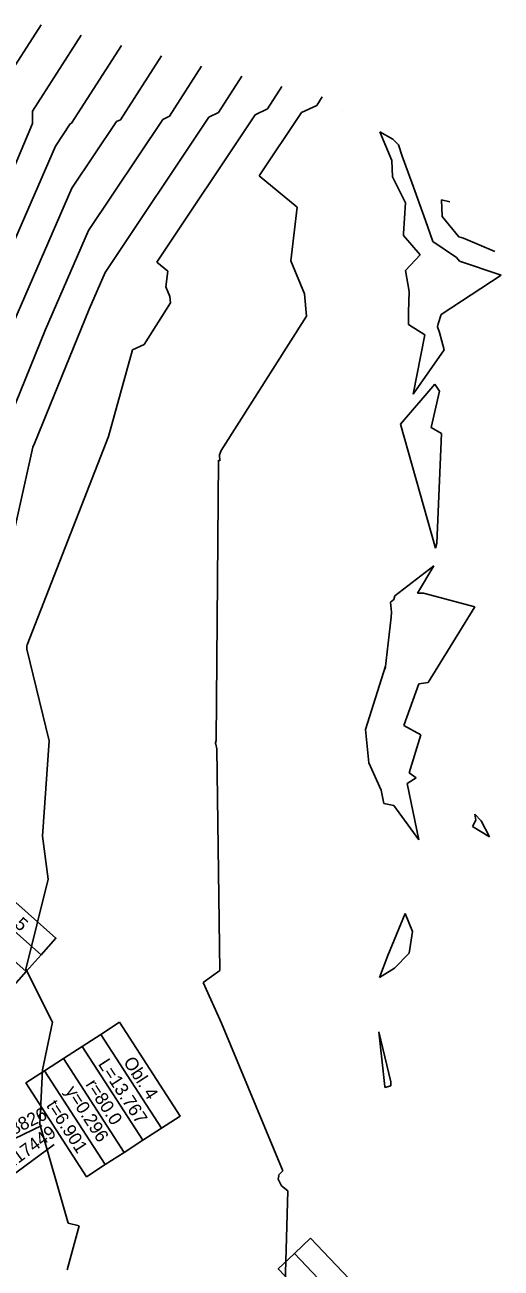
# Model space of a CAD drawing. Extents: x -549394 to -546608, y -1037055 to -1033629.
# Drawn here: x -547749.6 to -547621.7, y -1034785.5 to -1034451.5 of the extents above; entities that cross this region are included whole.
import ezdxf

# ---------------------------------------------------------------- set-up
doc = ezdxf.new("R2010")
doc.units = 0
for name, color, linetype in [('hlavni_vrst', 7, 'Continuous'), ('norm_vrst', 7, 'Continuous'), ('x_popis_oblouky_C21', 7, 'Continuous')]:
    doc.layers.add(name, color=color, linetype=linetype)

msp = doc.modelspace()

# ---------------------------------------------------------------- linework, layer by layer
at = {"layer": 'hlavni_vrst'}
for p, q in [((-547712.93, -1034459.83), (-547723.93, -1034477.01)), ((-547664.37, -1034474.53), (-547664.37, -1034474.53)), ((-547664.37, -1034474.53), (-547664.37, -1034474.53)), ((-547664.37, -1034474.53), (-547664.37, -1034474.53)), ((-547664.37, -1034474.53), (-547664.37, -1034474.53)), ((-547664.37, -1034474.53), (-547664.37, -1034474.53)), ((-547725.04, -1034477.54), (-547737, -1034495.44)), ((-547723.93, -1034477.01), (-547725.04, -1034477.54)), ((-547654.29, -1034480.26), (-547651.03, -1034487.95)), ((-547650.78, -1034482.28), (-547654.29, -1034480.26)), ((-547649.26, -1034483.72), (-547650.78, -1034482.28)), ((-547648.25, -1034486.79), (-547649.26, -1034483.72)), ((-547651.03, -1034487.95), (-547650.86, -1034492.35)), ((-547645.71, -1034493.87), (-547648.25, -1034486.79)), ((-547650.86, -1034492.35), (-547647.36, -1034499.32)), ((-547737, -1034495.44), (-547755.79, -1034538.71)), ((-547642.03, -1034504.09), (-547645.71, -1034493.87)), ((-547647.36, -1034499.32), (-547647.95, -1034507.59)), ((-547637.73, -1034498.55), (-547637.56, -1034503)), ((-547637.73, -1034498.55), (-547635.46, -1034499.05)), ((-547637.56, -1034503), (-547633.02, -1034508.52)), ((-547640.09, -1034509.72), (-547642.03, -1034504.09)), ((-547647.95, -1034507.59), (-547647.89, -1034508.12)), ((-547647.89, -1034508.12), (-547643.46, -1034513.35)), ((-547633.7, -1034514.04), (-547640.09, -1034509.72)), ((-547631.77, -1034508.8), (-547633.02, -1034508.52)), ((-547631.77, -1034508.8), (-547623.37, -1034512.46)), ((-547643.46, -1034513.35), (-547647.4, -1034517.48)), ((-547632.88, -1034515.03), (-547633.7, -1034514.04)), ((-547621.7, -1034518.79), (-547632.88, -1034515.03)), ((-547647.4, -1034517.48), (-547646.4, -1034523.19)), ((-547637.79, -1034529.35), (-547621.7, -1034518.79)), ((-547646.4, -1034523.19), (-547646.62, -1034528.71)), ((-547646.62, -1034528.71), (-547646.62, -1034532.01)), ((-547638.66, -1034531.86), (-547637.79, -1034529.35)), ((-547646.62, -1034532.01), (-547642.2, -1034534.79)), ((-547638.82, -1034532.68), (-547638.66, -1034531.86)), ((-547638.22, -1034534.17), (-547638.82, -1034532.68)), ((-547642.2, -1034534.79), (-547645.32, -1034550.77)), ((-547636.97, -1034538.86), (-547638.22, -1034534.17)), ((-547645.32, -1034550.77), (-547636.97, -1034538.86)), ((-547639.51, -1034548.01), (-547648.69, -1034558.82)), ((-547640.53, -1034559.73), (-547638.29, -1034549.93)), ((-547638.29, -1034549.93), (-547639.51, -1034548.01)), ((-547648.69, -1034558.82), (-547639.29, -1034592.12)), ((-547637.75, -1034561.3), (-547640.53, -1034559.73)), ((-547638.93, -1034590.72), (-547637.75, -1034561.3)), ((-547639.29, -1034592.12), (-547638.93, -1034590.72)), ((-547639.76, -1034596.89), (-547650.23, -1034604.9)), ((-547644.2, -1034604.16), (-547639.76, -1034596.89)), ((-547650.56, -1034605.87), (-547651.46, -1034606.64)), ((-547651.46, -1034606.64), (-547651.16, -1034609.31)), ((-547650.23, -1034604.9), (-547650.56, -1034605.87)), ((-547642.55, -1034604.2), (-547644.2, -1034604.16)), ((-547628.81, -1034607.85), (-547642.55, -1034604.2)), ((-547651.16, -1034609.31), (-547651.28, -1034610.61)), ((-547641.31, -1034628.2), (-547628.81, -1034607.85)), ((-547651.28, -1034610.61), (-547652.83, -1034624.61)), ((-547652.78, -1034623.84), (-547658.12, -1034640.81)), ((-547652.83, -1034624.61), (-547652.78, -1034623.84)), ((-547647.81, -1034639.72), (-547643.84, -1034628.54)), ((-547643.84, -1034628.54), (-547641.31, -1034628.2)), ((-547643.25, -1034642.23), (-547647.81, -1034639.72)), ((-547658.12, -1034640.81), (-547657.27, -1034649.76)), ((-547646.42, -1034652.42), (-547643.25, -1034642.23)), ((-547657.27, -1034649.76), (-547653.97, -1034657.12)), ((-547644.49, -1034653.75), (-547646.42, -1034652.42)), ((-547646.96, -1034655.34), (-547644.49, -1034653.75)), ((-547643.8, -1034670.42), (-547646.96, -1034655.34)), ((-547653.97, -1034657.12), (-547653.18, -1034660.66)), ((-547653.18, -1034660.66), (-547650.49, -1034661.19)), ((-547650.49, -1034661.19), (-547643.8, -1034670.42)), ((-547628.53, -1034665.15), (-547629.42, -1034666.89)), ((-547627.09, -1034665.35), (-547628.74, -1034663.55)), ((-547628.74, -1034663.55), (-547628.53, -1034665.15)), ((-547624.83, -1034669.63), (-547627.09, -1034665.35)), ((-547629.42, -1034666.89), (-547624.83, -1034669.63)), ((-547647.44, -1034690.27), (-547652.17, -1034701.54)), ((-547645.47, -1034695.06), (-547647.44, -1034690.27)), ((-547646.44, -1034700.91), (-547645.47, -1034695.06)), ((-547652.17, -1034701.54), (-547654.37, -1034707.44)), ((-547650.36, -1034704.96), (-547646.44, -1034700.91)), ((-547654.37, -1034707.44), (-547650.36, -1034704.96)), ((-547651.32, -1034735.47), (-547654.56, -1034721.99)), ((-547654.56, -1034721.99), (-547652.92, -1034736.68)), ((-547652.97, -1034736.94), (-547651.33, -1034736.48)), ((-547652.92, -1034736.68), (-547652.97, -1034736.94)), ((-547651.33, -1034736.48), (-547651.32, -1034735.47))]:
    msp.add_line(p, q, dxfattribs=at)
at = {"layer": 'norm_vrst'}
for p, q in [((-547745.28, -1034451.54), (-547755.34, -1034467.25)), ((-547734.5, -1034454.3), (-547747.57, -1034474.72)), ((-547723.72, -1034457.07), (-547737.1, -1034477.97)), ((-547702.15, -1034462.59), (-547710.76, -1034476.04)), ((-547691.37, -1034465.36), (-547697.59, -1034475.08)), ((-547680.58, -1034468.12), (-547684.42, -1034474.12)), ((-547669.8, -1034470.88), (-547671.25, -1034473.16)), ((-547747.57, -1034474.72), (-547747.6, -1034478.05)), ((-547700.19, -1034476.32), (-547728.1, -1034518.1)), ((-547687.76, -1034475.71), (-547714.19, -1034515.26)), ((-547710.76, -1034476.04), (-547712.62, -1034476.93)), ((-547697.59, -1034475.08), (-547700.19, -1034476.32)), ((-547684.42, -1034474.12), (-547687.76, -1034475.71)), ((-547675.34, -1034475.1), (-547686.66, -1034492.05)), ((-547671.25, -1034473.16), (-547675.34, -1034475.1)), ((-547747.6, -1034478.05), (-547766.85, -1034523.7)), ((-547737.47, -1034478.15), (-547741.45, -1034484.11)), ((-547737.1, -1034477.97), (-547737.47, -1034478.15)), ((-547712.62, -1034476.93), (-547732.55, -1034506.77)), ((-547741.45, -1034484.11), (-547759.32, -1034525.27)), ((-547686.66, -1034492.05), (-547676.52, -1034500.55)), ((-547676.52, -1034500.55), (-547678.22, -1034514.89)), ((-547732.55, -1034506.77), (-547744.08, -1034533.33)), ((-547714.19, -1034515.26), (-547711.24, -1034517.73)), ((-547678.22, -1034514.89), (-547674.56, -1034523.76)), ((-547728.1, -1034518.1), (-547732.38, -1034527.95)), ((-547711.24, -1034517.73), (-547711.73, -1034521.9)), ((-547711.73, -1034521.9), (-547710.67, -1034524.48)), ((-547710.49, -1034526.23), (-547717.61, -1034537.41)), ((-547710.67, -1034524.48), (-547710.49, -1034526.23)), ((-547674.56, -1034523.76), (-547673.95, -1034529.76)), ((-547732.38, -1034527.95), (-547747.04, -1034563.99)), ((-547673.95, -1034529.76), (-547696.93, -1034565.88)), ((-547744.08, -1034533.33), (-547753.53, -1034556.54)), ((-547720.77, -1034538.85), (-547727.2, -1034562.14)), ((-547717.61, -1034537.41), (-547720.77, -1034538.85)), ((-547727.2, -1034562.14), (-547749.02, -1034618.05)), ((-547747.51, -1034564.96), (-547753.98, -1034594)), ((-547747.04, -1034563.99), (-547747.51, -1034564.96)), ((-547696.93, -1034565.88), (-547697.39, -1034567.03)), ((-547697.59, -1034568.47), (-547698.29, -1034643.74)), ((-547697.26, -1034568.67), (-547697.59, -1034568.47)), ((-547697.39, -1034567.03), (-547697.26, -1034568.67)), ((-547749.07, -1034618.45), (-547749.08, -1034619.24)), ((-547749.08, -1034619.24), (-547743.1, -1034643.88)), ((-547749.02, -1034618.05), (-547749.07, -1034618.45)), ((-547743.1, -1034643.88), (-547744.93, -1034669.44)), ((-547698.23, -1034643.78), (-547698.43, -1034644.43)), ((-547698.43, -1034644.43), (-547698.42, -1034644.6)), ((-547698.42, -1034644.6), (-547698.35, -1034644.75)), ((-547698.35, -1034644.75), (-547698.07, -1034645.99)), ((-547698.29, -1034643.74), (-547698.23, -1034643.78)), ((-547698.07, -1034645.99), (-547697.29, -1034705.54)), ((-547744.93, -1034669.44), (-547743.38, -1034681)), ((-547743.38, -1034681), (-547749.38, -1034705.22)), ((-547749.38, -1034705.22), (-547742.26, -1034719.39)), ((-547697.29, -1034705.54), (-547701.78, -1034708.8)), ((-547701.78, -1034708.8), (-547696.84, -1034719.69)), ((-547742.26, -1034719.39), (-547744.87, -1034732.23)), ((-547696.84, -1034719.69), (-547680.3, -1034759.35)), ((-547744.87, -1034732.23), (-547745.63, -1034746.85)), ((-547745.63, -1034746.85), (-547737.97, -1034773.44)), ((-547680.3, -1034759.35), (-547681.49, -1034760.5)), ((-547681.39, -1034760.72), (-547681.63, -1034761.55)), ((-547681.63, -1034761.55), (-547680.73, -1034763.36)), ((-547681.49, -1034760.5), (-547681.39, -1034760.72)), ((-547680.73, -1034763.36), (-547678.99, -1034764.7)), ((-547678.99, -1034764.7), (-547680.13, -1034804.07)), ((-547737.97, -1034773.44), (-547735.03, -1034774.12)), ((-547735.03, -1034774.12), (-547738.25, -1034785.92))]:
    msp.add_line(p, q, dxfattribs=at)
at = {"layer": 'x_popis_oblouky_C21'}
for points in [[(-547763.75, -1034676.96), (-547741.29, -1034696.85), (-547745.27, -1034701.34), (-547767.73, -1034681.45)], [(-547767.73, -1034681.45), (-547745.27, -1034701.34), (-547749.25, -1034705.83), (-547771.71, -1034685.95)], [(-547771.71, -1034685.95), (-547749.25, -1034705.83), (-547753.22, -1034710.32), (-547775.69, -1034690.44)], [(-547724.18, -1034719.44), (-547707.88, -1034744.63), (-547712.92, -1034747.89), (-547729.22, -1034722.7)], [(-547729.22, -1034722.7), (-547712.92, -1034747.89), (-547717.96, -1034751.15), (-547734.25, -1034725.96)], [(-547734.25, -1034725.96), (-547717.96, -1034751.15), (-547722.99, -1034754.41), (-547739.29, -1034729.22)], [(-547739.29, -1034729.22), (-547722.99, -1034754.41), (-547728.03, -1034757.67), (-547744.33, -1034732.48)], [(-547744.33, -1034732.48), (-547728.03, -1034757.67), (-547733.07, -1034760.93), (-547749.37, -1034735.74)], [(-547672.89, -1034777.43), (-547652.23, -1034799.18), (-547656.58, -1034803.32), (-547677.24, -1034781.56)], [(-547677.24, -1034781.56), (-547656.58, -1034803.32), (-547660.93, -1034807.45), (-547681.59, -1034785.7)]]:
    msp.add_lwpolyline(points, close=True, dxfattribs=at)
for points in [[(-547745.04, -1034747.15), (-547782.31, -1034765.11)], [(-547741.8, -1034752.26), (-547775.1, -1034776.82)]]:
    msp.add_lwpolyline(points, dxfattribs=at)

# ---------------------------------------------------------------- texts
for s, rotation, p in [('Obl. 5', 318.5051, (-547760.06, -1034686.98)), ('L=13.767', 302.9271, (-547730.09, -1034730.66)), ('Obl. 4', 302.9271, (-547723.31, -1034730.09)), ('y=0.296', 302.9271, (-547738.95, -1034737.92)), ('r=80.0', 302.9271, (-547733.46, -1034736.17)), ('KT 0.18826', 25.7371, (-547765.17, -1034755.81)), ('t=6.901', 302.9271, (-547744.03, -1034741.76)), ('TK 0.17449', 36.4144, (-547760.4, -1034764.1))]:
    msp.add_text(s, height=3.5, rotation=rotation, dxfattribs=at).set_placement(p)

doc.saveas('drawing.dxf')
